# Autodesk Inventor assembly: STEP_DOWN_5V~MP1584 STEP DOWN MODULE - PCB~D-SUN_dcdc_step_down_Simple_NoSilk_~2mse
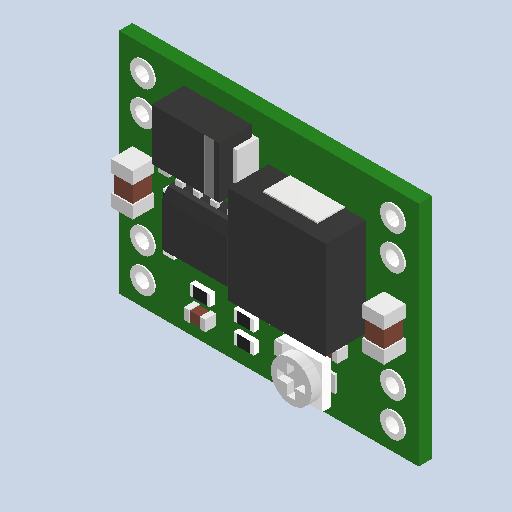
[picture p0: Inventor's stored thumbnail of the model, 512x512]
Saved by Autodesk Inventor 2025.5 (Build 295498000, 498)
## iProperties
Created: 2026-10
Part Number: STEP_DOWN_5V~MP1584 STEP DOWN MODULE - PCB~D-SUN_dcdc_step_down_Simple_NoSilk_~2mse
Document SubType Name: Assembly
Designer: Luis M
Author: Luis M
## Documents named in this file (4)
- C:\Users\Luis M\Downloads\3D_PCB1_2026-10-28\STEP_DOWN_5V~MP1584 STEP DOWN MODULE - PCB~D-SUN_dcdc_step_down_Simple_NoSilk_~2mse.iam
- C:\Users\Luis M\Downloads\3D_PCB1_2026-10-28\MP1584 STEP DOWN MODULE - PCB~D-SUN_dcdc_step_down_Simple_NoSilk_~pKhN.ipt
- C:\Users\Luis M\Downloads\3D_PCB1_2026-10-28\MP1584 STEP DOWN MODULE - PCB~D-SUN_dcdc_step_down_Simple_NoSilk_~pKhN_1.ipt
- C:\Users\Luis M\Downloads\3D_PCB1_2026-10-28\MP1584 STEP DOWN MODULE - PCB~D-SUN_dcdc_step_down_Simple_NoSilk_~pKhN_2.ipt
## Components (3 placed, 3 different names)
1. MP1584 STEP DOWN MODULE - PCB~D-SUN_dcdc_step_down_Simple_NoSilk_~pKhN_1
2. MP1584 STEP DOWN MODULE - PCB~D-SUN_dcdc_step_down_Simple_NoSilk_~pKhN_2
3. MP1584 STEP DOWN MODULE - PCB~D-SUN_dcdc_step_down_Simple_NoSilk_~pKhN_3
